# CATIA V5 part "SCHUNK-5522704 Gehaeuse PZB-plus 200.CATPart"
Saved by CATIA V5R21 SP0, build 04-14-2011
Part number: SCHUNK-5522704 Gehaeuse PZB-plus 200
Property "ParasolidId": 24
Property "PSOL_INSTNR": 5
Bounding box of the stored display mesh (mm): x -140.557 to 140.557, y 0 to 92, z -142.5 to 110
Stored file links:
  C:\Users\MIRCEA\Desktop\PRRO\CATIAV5\SCHUNK-5522704 Gehaeuse PZB-plus 200.CATPart
  C:\Program Files (x86)\Dassault Systemes\B21\intel_a\startup\materials\French\Catalog.CATMaterial
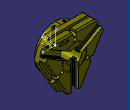
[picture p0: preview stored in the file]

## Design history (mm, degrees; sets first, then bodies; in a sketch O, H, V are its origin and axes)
AxisSystem1: origin (0, 0, 0), X (1, 0, 0), Y (0, 0, 1), Z (0, -1, 0)
Set1
  Point1: type OnPlane, Support zx-plane, H 0, V 0, Direction (-1, 0, 0)
  Line1: type PtDir, RefPoint Point1, Direction face of Solid1, Start 0, End 100
Body1 "SCHUNK-5522704 Gehaeuse PZB-plus 200(1)" (main body)
  Solid1: solid without history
